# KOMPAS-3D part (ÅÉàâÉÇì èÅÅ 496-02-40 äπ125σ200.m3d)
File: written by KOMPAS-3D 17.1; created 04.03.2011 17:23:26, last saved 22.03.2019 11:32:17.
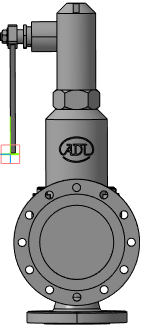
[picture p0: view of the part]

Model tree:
1. Плоскость XY
2. Плоскость ZX
3. Плоскость ZY
4. Ось X
5. Ось Y
6. Ось Z
7. Начало координат
8. Операция без истории:2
